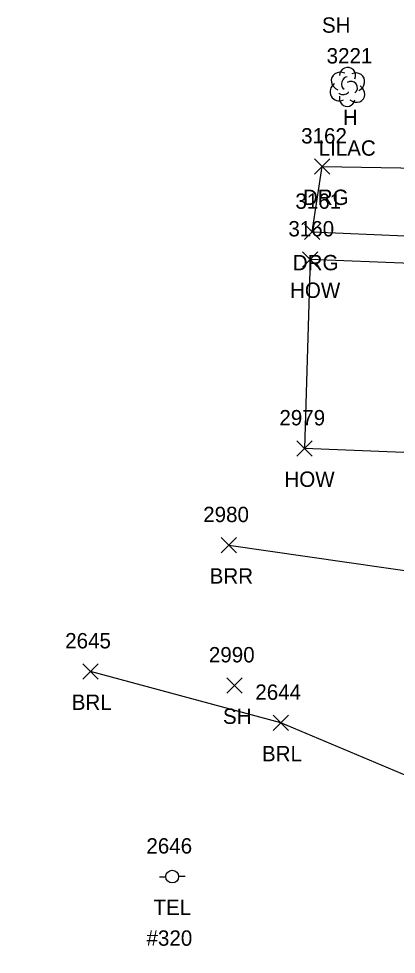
# Model space of a CAD drawing. Extents: x 1609623 to 1616187, y 756677 to 762826.
# Drawn here: x 1610488.8 to 1610537.9, y 762108.6 to 762230.4 of the extents above; entities that cross this region are included whole.
import ezdxf

# ---------------------------------------------------------------- set-up
doc = ezdxf.new("R2010")
doc.units = 0
for name, color, linetype in [('L_A', 7, 'Continuous'), ('L_C', 7, 'Continuous'), ('L_I', 7, 'Continuous'), ('L_TIC', 7, 'Continuous'), ('LABL', 7, 'Continuous'), ('LBC', 7, 'Continuous'), ('LTD', 7, 'Continuous'), ('R_A', 7, 'Continuous'), ('R_I', 7, 'Continuous'), ('R_TIC', 7, 'Continuous'), ('RDG', 7, 'Continuous'), ('U_A', 7, 'Continuous'), ('U_C', 7, 'Continuous'), ('U_I', 7, 'Continuous'), ('UP', 7, 'Continuous')]:
    doc.layers.add(name, color=color, linetype=linetype)

msp = doc.modelspace()

# ---------------------------------------------------------------- linework, layer by layer
at = {"layer": 'L_TIC'}
for points in [[(1610525.71, 762198.06), (1610527.71, 762200.06)], [(1610527.71, 762198.06), (1610525.71, 762200.06)], [(1610524.98, 762173.47), (1610526.98, 762175.47)], [(1610526.98, 762173.47), (1610524.98, 762175.47)], [(1610515.15, 762160.88), (1610517.15, 762162.88)], [(1610517.15, 762160.88), (1610515.15, 762162.88)], [(1610497.16, 762144.45), (1610499.16, 762146.45)], [(1610499.16, 762144.45), (1610497.16, 762146.45)], [(1610515.88, 762142.63), (1610517.88, 762144.63)], [(1610517.88, 762142.63), (1610515.88, 762144.63)], [(1610521.89, 762137.76), (1610523.89, 762139.76)], [(1610523.89, 762137.76), (1610521.89, 762139.76)]]:
    msp.add_lwpolyline(points, dxfattribs=at)
at = {"layer": 'LABL'}
for points in [[(1610516.15, 762161.88), (1610541.71, 762158.2), (1610566.25, 762154.56), (1610579.97, 762123.99), (1610582.03, 762101.45), (1610567.79, 762100.81), (1610552.43, 762130.39)], [(1610470.36, 762115.52), (1610475.23, 762088.99), (1610479.69, 762062.39), (1610486.02, 762049.51), (1610500.72, 762036.95), (1610516.41, 762053.54), (1610531.56, 762075.46), (1610545, 762093.74), (1610548.44, 762128.03), (1610522.89, 762138.76), (1610498.16, 762145.45)]]:
    msp.add_lwpolyline(points, dxfattribs=at)
at = {"layer": 'LBC'}
for points in [[(1610526.71, 762199.06), (1610525.98, 762174.47)], [(1610557.66, 762197.19), (1610557.35, 762197.83), (1610526.71, 762199.06)], [(1610544.27, 762173.71), (1610525.98, 762174.47)]]:
    msp.add_lwpolyline(points, dxfattribs=at)
at = {"layer": 'LTD'}
msp.add_line((1610531.54, 762221.56), (1610531.54, 762221.56), dxfattribs=at)
msp.add_line((1610531.54, 762221.56), (1610531.54, 762221.56), dxfattribs=at)
msp.add_arc((1610531.58, 762223), 1.05, 335.5272, 180.9563, dxfattribs=at)
for centre, major_axis, ratio, start_param, end_param in [((1610530.75, 762222.23), (1.21, -0.51), 0.895232, 1.570796, 4.712389), ((1610532.58, 762222.15), (-1.14, -0.48), 0.949671, 1.570796, 4.712389), ((1610531.33, 762222.02), (-0.208, -0.792), 0.645439, 3.141593, 6.283185), ((1610532.04, 762221.4), (-0.5, 0.667), 0.989748, 3.141593, 6.283185), ((1610530.45, 762220.86), (0.58, -1.04), 0.959034, 3.141593, 6.283185), ((1610532.54, 762220.73), (-1.09, 0.79), 0.841452, 1.570796, 4.712389), ((1610531.54, 762220.06), (0.26, 1.06), 0.942809, 1.570796, 4.712389), ((1610531.08, 762220.81), (-0.625, -0.083), 0.423636, 0, 3.141593)]:
    msp.add_ellipse(centre, major_axis=major_axis, ratio=ratio, start_param=start_param, end_param=end_param, dxfattribs=at)
at = {"layer": 'R_TIC'}
for points in [[(1610527.28, 762210.15), (1610529.28, 762212.15)], [(1610529.28, 762210.15), (1610527.28, 762212.15)], [(1610525.96, 762201.65), (1610527.96, 762203.65)], [(1610527.96, 762201.65), (1610525.96, 762203.65)]]:
    msp.add_lwpolyline(points, dxfattribs=at)
at = {"layer": 'RDG'}
for points in [[(1610526.96, 762202.65), (1610528.28, 762211.15), (1610558.98, 762210.64), (1610580.61, 762210.76), (1610589.95, 762212.25), (1610595.04, 762218.43)], [(1610526.96, 762202.65), (1610563.24, 762201.08)]]:
    msp.add_lwpolyline(points, dxfattribs=at)
at = {"layer": 'UP'}
for p, q in [((1610507.11, 762118.75), (1610507.94, 762118.75)), ((1610508.77, 762118.76), (1610508.77, 762118.76)), ((1610510.44, 762118.76), (1610509.61, 762118.76)), ((1610509.61, 762118.76), (1610509.61, 762118.76)), ((1610510.44, 762118.76), (1610510.44, 762118.76))]:
    msp.add_line(p, q, dxfattribs=at)
msp.add_circle((1610508.77, 762118.76), 0.833, dxfattribs=at)

# ---------------------------------------------------------------- texts
at = {"layer": 'L_A'}
for s, p in [('SH', (1610528.24, 762228.56)), ('H', (1610530.97, 762216.56)), ('HOW', (1610524.09, 762194.06)), ('HOW', (1610523.36, 762169.47)), ('BRR', (1610513.64, 762156.88)), ('BRL', (1610495.7, 762140.45)), ('SH', (1610515.37, 762138.63)), ('BRL', (1610520.44, 762133.76))]:
    msp.add_text(s, height=2, dxfattribs=at).set_placement(p)
at = {"layer": 'L_C'}
msp.add_text('LILAC', height=2, dxfattribs=at).set_placement((1610527.81, 762212.56))
at = {"layer": 'L_I'}
for s, p in [('3221', (1610528.85, 762224.56)), ('3160', (1610523.88, 762202.06)), ('2979', (1610522.71, 762177.47)), ('2980', (1610512.8, 762164.88)), ('2645', (1610494.85, 762148.45)), ('2990', (1610513.54, 762146.63)), ('2644', (1610519.58, 762141.76))]:
    msp.add_text(s, height=2, dxfattribs=at).set_placement(p)
at = {"layer": 'R_A'}
for p in [(1610525.77, 762206.15), (1610524.45, 762197.65)]:
    msp.add_text('DRG', height=2, dxfattribs=at).set_placement(p)
at = {"layer": 'R_I'}
for s, p in [('3162', (1610525.54, 762214.15)), ('3161', (1610524.79, 762205.65))]:
    msp.add_text(s, height=2, dxfattribs=at).set_placement(p)
at = {"layer": 'U_A'}
msp.add_text('TEL', height=2, dxfattribs=at).set_placement((1610506.33, 762113.76))
at = {"layer": 'U_C'}
msp.add_text('#320', height=2, dxfattribs=at).set_placement((1610505.43, 762109.76))
at = {"layer": 'U_I'}
msp.add_text('2646', height=2, dxfattribs=at).set_placement((1610505.41, 762121.76))

doc.saveas('drawing.dxf')
